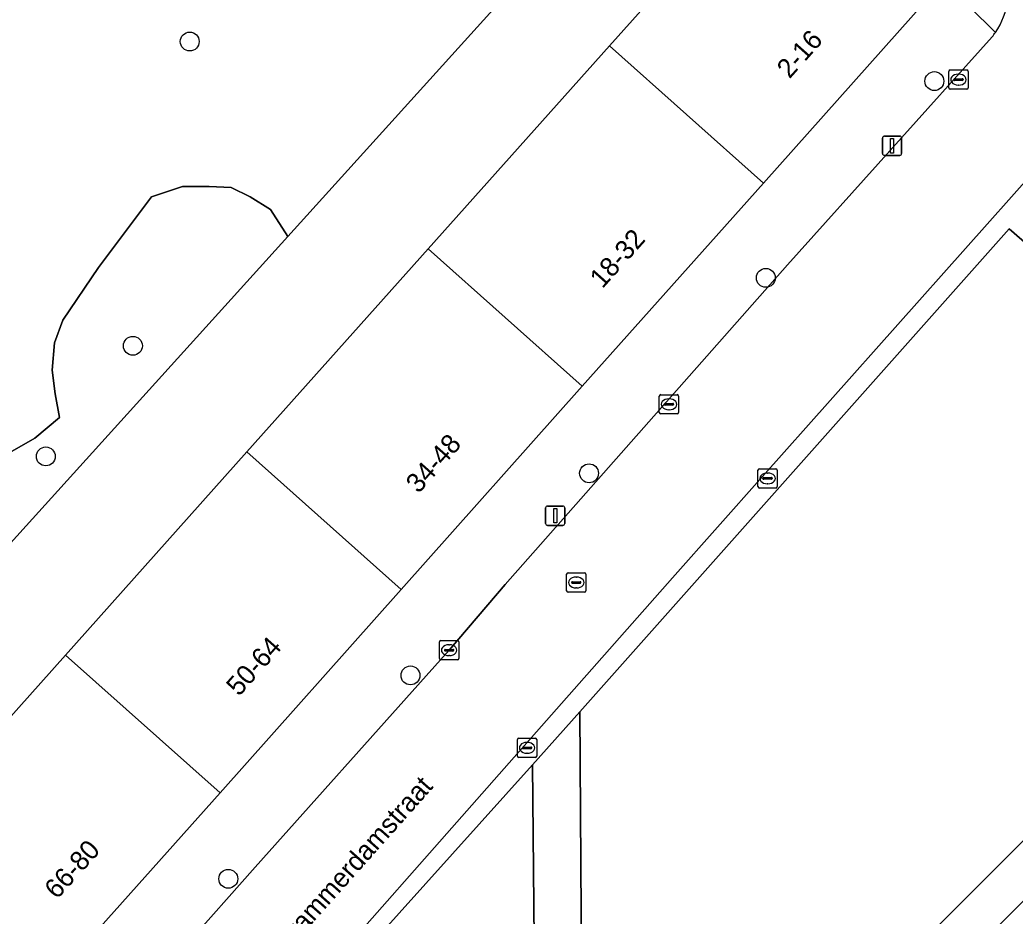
# Model space of a CAD drawing. Extents: x 159888 to 160761, y 384031 to 384750.
# Drawn here: x 160333.6 to 160385.2, y 384297.8 to 384344.2 of the extents above; entities that cross this region are included whole.
import ezdxf

# ---------------------------------------------------------------- set-up
doc = ezdxf.new("R2010")
doc.units = 0
for name, color, linetype in [('IMGEO_Boom', 7, 'Continuous'), ('IMGEO_Erf', 7, 'Continuous'), ('IMGEO_Groenvoorziening', 7, 'Continuous'), ('IMGEO_Kolk', 7, 'Continuous'), ('IMGEO_Lichtmast', 7, 'Continuous'), ('IMGEO_Openbare_ruimte_label', 7, 'Continuous'), ('IMGEO_Pand', 7, 'Continuous'), ('IMGEO_Pand_nummerreeks', 7, 'Continuous'), ('IMGEO_Rijbaan_lokaal_open', 7, 'Continuous'), ('IMGEO_Rioolput', 7, 'Continuous'), ('IMGEO_Voetpad_halfverhard', 7, 'Continuous'), ('IMGEO_Voetpad_open', 7, 'Continuous')]:
    doc.layers.add(name, color=color, linetype=linetype)

msp = doc.modelspace()

# ---------------------------------------------------------------- linework, layer by layer
at = {"layer": 'IMGEO_Boom'}
for centre in [(160342.399, 384343.13), (160380.968, 384341.08), (160372.236, 384330.889), (160339.456, 384327.37), (160334.945, 384321.643), (160363.084, 384320.767), (160353.833, 384310.3), (160344.397, 384299.767)]:
    msp.add_circle(centre, 0.489, dxfattribs=at)
at = {"layer": 'IMGEO_Erf'}
for points in [[(160354.755, 384332.386), (160364.148, 384342.901), (160373.493, 384353.362), (160374.576, 384354.663), (160370.91, 384358.966), (160359.082, 384345.88), (160347.472, 384333.034), (160321.993, 384304.881), (160326.574, 384300.84), (160335.968, 384311.355), (160345.361, 384321.871)], [(160407.134, 384312.362), (160404.095, 384316.885), (160401.57, 384314.532), (160372.039, 384285.135), (160362.772, 384285.007), (160362.837, 384279.095), (160351.699, 384267.85), (160345.439, 384274.748), (160345.355, 384284.72), (160341.199, 384284.583), (160337.275, 384280.219), (160336.483, 384279.562), (160360.504, 384250.764), (160363.191, 384253.558), (160355.746, 384260.844), (160365.773, 384270.9), (160375.799, 384280.956), (160385.826, 384291.012), (160395.852, 384301.068), (160405.753, 384310.998)]]:
    msp.add_lwpolyline(points, close=True, dxfattribs=at)
at = {"layer": 'IMGEO_Groenvoorziening'}
for points in [[(160346.601, 384346.671), (160342.877, 384351.012), (160335.546, 384346.476), (160334.832, 384346.722), (160331.336, 384349.545), (160314.321, 384328.458), (160318.416, 384324.982), (160315.546, 384321.854), (160314.241, 384320.516), (160319.822, 384312.651), (160327.142, 384317.932), (160330.707, 384320.49), (160334.376, 384322.584), (160335.646, 384323.663), (160335.437, 384324.891), (160335.278, 384326.11), (160335.396, 384327.525), (160335.828, 384328.701), (160337.68, 384331.434), (160340.425, 384335.089)], [(160340.425, 384335.089), (160342.026, 384335.628), (160343.406, 384335.615), (160344.546, 384335.562), (160345.527, 384335.084), (160346.587, 384334.422), (160347.472, 384333.034), (160359.082, 384345.88), (160357.029, 384347.606), (160355.178, 384349.66), (160350.544, 384346.722)], [(160321.993, 384304.881), (160347.472, 384333.034), (160346.587, 384334.422), (160345.527, 384335.084), (160344.546, 384335.562), (160343.406, 384335.615), (160342.026, 384335.628), (160340.425, 384335.089), (160337.68, 384331.434), (160335.828, 384328.701), (160335.396, 384327.525), (160335.278, 384326.11), (160335.437, 384324.891), (160335.646, 384323.663), (160334.376, 384322.584), (160330.707, 384320.49)]]:
    msp.add_lwpolyline(points, dxfattribs=at)
for points in [[(160362.609, 384308.421), (160362.749, 384287.577), (160371.557, 384287.736), (160402.753, 384318.884), (160399.209, 384324.159), (160391.497, 384335.159), (160387.746, 384330.904), (160384.849, 384333.43)], [(160343.576, 384287.226), (160360.319, 384287.543), (160360.161, 384305.668)]]:
    msp.add_lwpolyline(points, close=True, dxfattribs=at)
at = {"layer": 'IMGEO_Kolk'}
for p, q in [((160381.716, 384340.73), (160381.716, 384341.582)), ((160381.791, 384341.656), (160382.643, 384341.656)), ((160382.204, 384341.436), (160382.229, 384341.436)), ((160382.717, 384341.582), (160382.717, 384340.73)), ((160381.975, 384341.15), (160381.975, 384341.162)), ((160382.413, 384341.113), (160382.015, 384341.113)), ((160382.018, 384341.199), (160382.416, 384341.199)), ((160382.227, 384340.876), (160382.202, 384340.876)), ((160382.459, 384341.162), (160382.459, 384341.15)), ((160382.643, 384340.656), (160381.791, 384340.656)), ((160366.722, 384323.914), (160366.722, 384324.766)), ((160366.797, 384324.84), (160367.649, 384324.84)), ((160367.723, 384324.766), (160367.723, 384323.914)), ((160366.981, 384324.334), (160366.981, 384324.346)), ((160367.419, 384324.297), (160367.021, 384324.297)), ((160367.024, 384324.383), (160367.422, 384324.383)), ((160367.21, 384324.62), (160367.235, 384324.62)), ((160367.465, 384324.346), (160367.465, 384324.334)), ((160367.649, 384323.84), (160366.797, 384323.84)), ((160367.233, 384324.06), (160367.208, 384324.06)), ((160371.83, 384320.077), (160371.83, 384320.929)), ((160371.905, 384321.003), (160372.757, 384321.003)), ((160372.318, 384320.783), (160372.343, 384320.783)), ((160372.831, 384320.929), (160372.831, 384320.077)), ((160372.089, 384320.497), (160372.089, 384320.509)), ((160372.527, 384320.46), (160372.129, 384320.46)), ((160372.132, 384320.546), (160372.53, 384320.546)), ((160372.341, 384320.223), (160372.316, 384320.223)), ((160372.573, 384320.509), (160372.573, 384320.497)), ((160372.757, 384320.003), (160371.905, 384320.003)), ((160355.335, 384311.18), (160355.335, 384312.032)), ((160355.41, 384312.106), (160356.262, 384312.106)), ((160355.823, 384311.886), (160355.848, 384311.886)), ((160356.336, 384312.032), (160356.336, 384311.18)), ((160355.594, 384311.6), (160355.594, 384311.612)), ((160356.032, 384311.563), (160355.634, 384311.563)), ((160355.637, 384311.649), (160356.035, 384311.649)), ((160356.078, 384311.612), (160356.078, 384311.6)), ((160356.262, 384311.106), (160355.41, 384311.106)), ((160355.846, 384311.326), (160355.821, 384311.326)), ((160359.372, 384306.122), (160359.372, 384306.974)), ((160359.447, 384307.048), (160360.299, 384307.048)), ((160359.86, 384306.828), (160359.885, 384306.828)), ((160360.373, 384306.974), (160360.373, 384306.122)), ((160359.631, 384306.542), (160359.631, 384306.554)), ((160360.069, 384306.505), (160359.671, 384306.505)), ((160359.674, 384306.591), (160360.072, 384306.591)), ((160359.883, 384306.268), (160359.858, 384306.268)), ((160360.115, 384306.554), (160360.115, 384306.542)), ((160360.299, 384306.048), (160359.447, 384306.048))]:
    msp.add_line(p, q, dxfattribs=at)
for points in [[(160381.716, 384340.73), (160381.716, 384341.582)], [(160381.791, 384341.656), (160382.643, 384341.656)], [(160382.717, 384341.582), (160382.717, 384340.73)], [(160382.643, 384340.656), (160381.791, 384340.656)], [(160366.722, 384323.914), (160366.722, 384324.766)], [(160366.797, 384324.84), (160367.649, 384324.84)], [(160367.723, 384324.766), (160367.723, 384323.914)], [(160367.649, 384323.84), (160366.797, 384323.84)], [(160371.83, 384320.077), (160371.83, 384320.929)], [(160371.905, 384321.003), (160372.757, 384321.003)], [(160372.831, 384320.929), (160372.831, 384320.077)], [(160372.757, 384320.003), (160371.905, 384320.003)], [(160355.335, 384311.18), (160355.335, 384312.032)], [(160355.41, 384312.106), (160356.262, 384312.106)], [(160356.336, 384312.032), (160356.336, 384311.18)], [(160356.262, 384311.106), (160355.41, 384311.106)], [(160359.372, 384306.122), (160359.372, 384306.974)], [(160359.447, 384307.048), (160360.299, 384307.048)], [(160360.373, 384306.974), (160360.373, 384306.122)], [(160360.299, 384306.048), (160359.447, 384306.048)]]:
    msp.add_lwpolyline(points, dxfattribs=at)
for centre, radius, start, end in [((160381.793, 384341.58), 0.0765, 91.552, 178.448), ((160381.793, 384341.58), 0.0765, 91.552, 178.448), ((160382.641, 384341.58), 0.0765, 1.552, 88.448), ((160382.641, 384341.58), 0.0765, 1.552, 88.448), ((160382.015, 384341.159), 0.0403, 85.8775, 175.7526), ((160382.012, 384341.149), 0.0366, 178.938, 274.7102), ((160382.416, 384341.156), 0.043, 264.8664, 352.4533), ((160382.42, 384341.161), 0.0386, 1.7309, 96.639), ((160381.793, 384340.732), 0.0765, 181.552, 268.448), ((160381.793, 384340.732), 0.0765, 181.552, 268.448), ((160382.641, 384340.732), 0.0765, 271.552, 358.448), ((160382.641, 384340.732), 0.0765, 271.552, 358.448), ((160366.799, 384324.764), 0.0765, 91.552, 178.448), ((160366.799, 384324.764), 0.0765, 91.552, 178.448), ((160367.647, 384324.764), 0.0765, 1.552, 88.448), ((160367.647, 384324.764), 0.0765, 1.552, 88.448), ((160367.021, 384324.343), 0.0403, 85.8775, 175.7526), ((160367.018, 384324.333), 0.0366, 178.938, 274.7102), ((160367.422, 384324.34), 0.043, 264.8664, 352.4533), ((160367.426, 384324.345), 0.0386, 1.7309, 96.639), ((160366.799, 384323.916), 0.0765, 181.552, 268.448), ((160366.799, 384323.916), 0.0765, 181.552, 268.448), ((160367.647, 384323.916), 0.0765, 271.552, 358.448), ((160367.647, 384323.916), 0.0765, 271.552, 358.448), ((160371.907, 384320.927), 0.0765, 91.552, 178.448), ((160371.907, 384320.927), 0.0765, 91.552, 178.448), ((160372.755, 384320.927), 0.0765, 1.552, 88.448), ((160372.755, 384320.927), 0.0765, 1.552, 88.448), ((160372.129, 384320.506), 0.0403, 85.8775, 175.7526), ((160372.126, 384320.496), 0.0366, 178.938, 274.7102), ((160372.53, 384320.503), 0.043, 264.8664, 352.4533), ((160372.534, 384320.508), 0.0386, 1.7309, 96.639), ((160371.907, 384320.079), 0.0765, 181.552, 268.448), ((160371.907, 384320.079), 0.0765, 181.552, 268.448), ((160372.755, 384320.079), 0.0765, 271.552, 358.448), ((160372.755, 384320.079), 0.0765, 271.552, 358.448), ((160355.412, 384312.03), 0.0765, 91.552, 178.448), ((160355.412, 384312.03), 0.0765, 91.552, 178.448), ((160356.26, 384312.03), 0.0765, 1.552, 88.448), ((160356.26, 384312.03), 0.0765, 1.552, 88.448), ((160355.634, 384311.609), 0.0403, 85.8775, 175.7526), ((160355.631, 384311.599), 0.0366, 178.938, 274.7102), ((160356.035, 384311.606), 0.043, 264.8664, 352.4533), ((160356.039, 384311.611), 0.0386, 1.7309, 96.639), ((160355.412, 384311.182), 0.0765, 181.552, 268.448), ((160355.412, 384311.182), 0.0765, 181.552, 268.448), ((160356.26, 384311.182), 0.0765, 271.552, 358.448), ((160356.26, 384311.182), 0.0765, 271.552, 358.448), ((160359.449, 384306.972), 0.0765, 91.552, 178.448), ((160359.449, 384306.972), 0.0765, 91.552, 178.448), ((160360.297, 384306.972), 0.0765, 1.552, 88.448), ((160360.297, 384306.972), 0.0765, 1.552, 88.448), ((160359.671, 384306.551), 0.0403, 85.8775, 175.7526), ((160359.668, 384306.541), 0.0366, 178.938, 274.7102), ((160360.072, 384306.548), 0.043, 264.8664, 352.4533), ((160360.076, 384306.553), 0.0386, 1.7309, 96.639), ((160359.449, 384306.124), 0.0765, 181.552, 268.448), ((160359.449, 384306.124), 0.0765, 181.552, 268.448), ((160360.297, 384306.124), 0.0765, 271.552, 358.448), ((160360.297, 384306.124), 0.0765, 271.552, 358.448)]:
    msp.add_arc(centre, radius, start, end, dxfattribs=at)
for centre, major_axis, ratio, start_param, end_param in [((160382.203, 384341.156), (-0.387, 0.002), 0.722429, 4.712389, 7.853982), ((160382.228, 384341.156), (-0.39, 0.002), 0.717154, 1.570796, 4.712389), ((160367.209, 384324.34), (-0.387, 0.002), 0.722429, 4.712389, 7.853982), ((160367.234, 384324.34), (-0.39, 0.002), 0.717154, 1.570796, 4.712389), ((160372.317, 384320.503), (-0.387, 0.002), 0.722429, 4.712389, 7.853982), ((160372.342, 384320.503), (-0.39, 0.002), 0.717154, 1.570796, 4.712389), ((160355.822, 384311.606), (-0.387, 0.002), 0.722429, 4.712389, 7.853982), ((160355.847, 384311.606), (-0.39, 0.002), 0.717154, 1.570796, 4.712389), ((160359.859, 384306.548), (-0.387, 0.002), 0.722429, 4.712389, 7.853982), ((160359.884, 384306.548), (-0.39, 0.002), 0.717154, 1.570796, 4.712389)]:
    msp.add_ellipse(centre, major_axis=major_axis, ratio=ratio, start_param=start_param, end_param=end_param, dxfattribs=at)
at = {"layer": 'IMGEO_Lichtmast'}
for p, q in [((160378.382, 384338.23), (160379.172, 384338.23)), ((160379.172, 384338.23), (160378.382, 384338.23)), ((160378.282, 384337.33), (160378.282, 384338.13)), ((160378.282, 384338.13), (160378.282, 384337.33)), ((160379.272, 384338.13), (160379.272, 384337.33)), ((160379.272, 384337.33), (160379.272, 384338.13)), ((160379.172, 384337.23), (160378.382, 384337.23)), ((160378.382, 384337.23), (160379.172, 384337.23)), ((160360.835, 384318.171), (160360.835, 384318.971)), ((160360.835, 384318.971), (160360.835, 384318.171)), ((160360.935, 384319.071), (160361.725, 384319.071)), ((160361.725, 384319.071), (160360.935, 384319.071)), ((160361.825, 384318.971), (160361.825, 384318.171)), ((160361.825, 384318.171), (160361.825, 384318.971)), ((160361.725, 384318.071), (160360.935, 384318.071)), ((160360.935, 384318.071), (160361.725, 384318.071))]:
    msp.add_line(p, q, dxfattribs=at)
for points in [[(160378.702, 384338.105), (160378.852, 384338.105), (160378.852, 384337.355), (160378.702, 384337.355), (160378.702, 384338.105)], [(160361.255, 384318.946), (160361.405, 384318.946), (160361.405, 384318.196), (160361.255, 384318.196), (160361.255, 384318.946)]]:
    msp.add_lwpolyline(points, dxfattribs=at)
for centre, start, end in [((160378.382, 384338.13), 90, 180), ((160378.382, 384338.13), 90, 180), ((160379.172, 384338.13), 0, 90), ((160379.172, 384338.13), 360, 90), ((160378.382, 384337.33), 180, 270), ((160378.382, 384337.33), 180, 270), ((160379.172, 384337.33), 270, 0), ((160379.172, 384337.33), 270, 0), ((160360.935, 384318.971), 90, 180), ((160360.935, 384318.971), 90, 180), ((160361.725, 384318.971), 0, 90), ((160361.725, 384318.971), 360, 90), ((160360.935, 384318.171), 180, 270), ((160360.935, 384318.171), 180, 270), ((160361.725, 384318.171), 270, 0), ((160361.725, 384318.171), 270, 0)]:
    msp.add_arc(centre, 0.1, start, end, dxfattribs=at)
at = {"layer": 'IMGEO_Pand'}
for points in [[(160364.148, 384342.901), (160372.116, 384335.798), (160381.45, 384346.268), (160373.493, 384353.362)], [(160354.755, 384332.386), (160362.733, 384325.273), (160372.116, 384335.798), (160364.148, 384342.901)], [(160354.755, 384332.386), (160345.361, 384321.871), (160353.35, 384314.748), (160362.733, 384325.273)], [(160343.967, 384304.224), (160353.35, 384314.748), (160345.361, 384321.871), (160335.968, 384311.355)], [(160343.967, 384304.224), (160335.968, 384311.355), (160326.574, 384300.84), (160330.004, 384297.782), (160334.584, 384293.699)]]:
    msp.add_lwpolyline(points, close=True, dxfattribs=at)
at = {"layer": 'IMGEO_Rijbaan_lokaal_open'}
for points in [[(160383.963, 384343.377), (160373.369, 384331.56), (160358.734, 384315.005), (160355.836, 384311.606), (160354.645, 384310.274), (160345.783, 384300.371), (160342.137, 384296.259), (160335.028, 384288.426), (160333.603, 384286.83), (160331.755, 384284.956), (160329.563, 384283.059), (160327.209, 384281.326), (160320.493, 384276.397), (160319.163, 384275.415), (160318.454, 384274.829), (160317.834, 384274.312)], [(160367.398, 384315.345), (160372.06, 384320.608), (160386.091, 384336.349), (160387.995, 384338.559)], [(160316.352, 384271.463), (160319.071, 384267.868), (160319.303, 384267.551), (160320.163, 384268.187), (160325.613, 384272.322), (160329.833, 384275.348), (160333.576, 384278.079), (160335.984, 384279.983), (160336.104, 384280.105), (160336.716, 384280.731), (160338.331, 384282.617), (160345.01, 384289.972), (160361.399, 384308.557), (160367.398, 384315.345)]]:
    msp.add_lwpolyline(points, dxfattribs=at)
for centre, radius, start, end in [((160381.036, 384345.741), 3.762, 325.3172, 353.4534), ((160381.37, 384345.493), 3.347, 320.7858, 325.5567)]:
    msp.add_arc(centre, radius, start, end, dxfattribs=at)
at = {"layer": 'IMGEO_Rioolput'}
for p, q in [((160361.92, 384314.685), (160361.92, 384315.537)), ((160361.995, 384315.611), (160362.847, 384315.611)), ((160362.921, 384315.537), (160362.921, 384314.685)), ((160362.179, 384315.105), (160362.179, 384315.117)), ((160362.617, 384315.068), (160362.219, 384315.068)), ((160362.222, 384315.154), (160362.62, 384315.154)), ((160362.408, 384315.391), (160362.433, 384315.391)), ((160362.663, 384315.117), (160362.663, 384315.105)), ((160362.847, 384314.611), (160361.995, 384314.611)), ((160362.431, 384314.831), (160362.406, 384314.831))]:
    msp.add_line(p, q, dxfattribs=at)
for points in [[(160361.92, 384314.685), (160361.92, 384315.537)], [(160361.995, 384315.611), (160362.847, 384315.611)], [(160362.921, 384315.537), (160362.921, 384314.685)], [(160362.847, 384314.611), (160361.995, 384314.611)]]:
    msp.add_lwpolyline(points, dxfattribs=at)
for centre, radius, start, end in [((160361.997, 384315.535), 0.0765, 91.552, 178.448), ((160361.997, 384315.535), 0.0765, 91.552, 178.448), ((160362.845, 384315.535), 0.0765, 1.552, 88.448), ((160362.845, 384315.535), 0.0765, 1.552, 88.448), ((160362.219, 384315.114), 0.0403, 85.8775, 175.7526), ((160362.216, 384315.104), 0.0366, 178.938, 274.7102), ((160362.62, 384315.111), 0.043, 264.8664, 352.4533), ((160362.624, 384315.116), 0.0386, 1.7309, 96.639), ((160361.997, 384314.687), 0.0765, 181.552, 268.448), ((160361.997, 384314.687), 0.0765, 181.552, 268.448), ((160362.845, 384314.687), 0.0765, 271.552, 358.448), ((160362.845, 384314.687), 0.0765, 271.552, 358.448)]:
    msp.add_arc(centre, radius, start, end, dxfattribs=at)
for centre, major_axis, ratio, start_param, end_param in [((160362.407, 384315.111), (-0.387, 0.002), 0.722429, 4.712389, 7.853982), ((160362.432, 384315.111), (-0.39, 0.002), 0.717154, 1.570796, 4.712389)]:
    msp.add_ellipse(centre, major_axis=major_axis, ratio=ratio, start_param=start_param, end_param=end_param, dxfattribs=at)
at = {"layer": 'IMGEO_Voetpad_halfverhard'}
msp.add_lwpolyline([(160401.57, 384314.532), (160404.095, 384316.885), (160402.753, 384318.884), (160371.557, 384287.736), (160362.749, 384287.577), (160362.609, 384308.421), (160360.161, 384305.668), (160360.319, 384287.543), (160343.576, 384287.226), (160341.199, 384284.583), (160345.355, 384284.72), (160362.772, 384285.007), (160372.039, 384285.135)], close=True, dxfattribs=at)
at = {"layer": 'IMGEO_Voetpad_open'}
for points in [[(160353.925, 384379.322), (160350.858, 384375.538), (160351.227, 384374.884), (160353.151, 384372.682), (160356.226, 384375.192), (160358.705, 384372.155), (160359.244, 384372.659), (160367.457, 384363.019), (160369.023, 384361.181), (160370.91, 384358.966), (160374.576, 384354.663), (160373.493, 384353.362), (160381.45, 384346.268), (160384.13, 384343.6)], [(160384.13, 384343.6), (160381.45, 384346.268), (160372.116, 384335.798), (160362.733, 384325.273), (160353.35, 384314.748), (160343.967, 384304.224), (160334.584, 384293.699), (160331.935, 384291.025), (160329.749, 384288.44), (160312.595, 384275.443), (160316.352, 384271.463)], [(160354.645, 384310.274), (160355.836, 384311.606), (160358.734, 384315.005), (160373.369, 384331.56), (160383.963, 384343.377)], [(160333.927, 384277.642), (160336.483, 384279.562), (160337.275, 384280.219), (160341.199, 384284.583), (160343.576, 384287.226), (160360.161, 384305.668), (160362.609, 384308.421), (160384.849, 384333.43), (160387.746, 384330.904), (160391.497, 384335.159), (160388.52, 384338.959)], [(160387.995, 384338.559), (160386.091, 384336.349), (160372.06, 384320.608), (160367.398, 384315.345), (160361.399, 384308.557), (160345.01, 384289.972), (160338.331, 384282.617), (160336.716, 384280.731), (160336.104, 384280.105), (160335.984, 384279.983), (160333.576, 384278.079), (160329.833, 384275.348), (160325.613, 384272.322), (160320.163, 384268.187), (160319.303, 384267.551), (160318.92, 384266.275), (160333.927, 384277.642)], [(160317.834, 384274.312), (160318.454, 384274.829), (160319.163, 384275.415), (160320.493, 384276.397), (160327.209, 384281.326), (160329.563, 384283.059), (160331.755, 384284.956), (160331.394, 384285.301), (160334.662, 384288.766), (160335.028, 384288.426), (160342.137, 384296.259), (160345.783, 384300.371), (160354.645, 384310.274)]]:
    msp.add_lwpolyline(points, dxfattribs=at)
for centre, radius, start, end in [((160381.036, 384345.741), 3.762, 325.3172, 353.4534), ((160381.37, 384345.493), 3.347, 320.7858, 325.5567)]:
    msp.add_arc(centre, radius, start, end, dxfattribs=at)

# ---------------------------------------------------------------- texts
at = {"layer": 'IMGEO_Openbare_ruimte_label'}
msp.add_text('Swammerdamstraat', height=1, rotation=48.3236, dxfattribs=at).set_placement((160347.088, 384295.578))
at = {"layer": 'IMGEO_Pand_nummerreeks'}
for s, rotation, p in [('2-16', 48.3665, (160373.467, 384341.166)), ('18-32', 48.221, (160363.775, 384330.301)), ('34-48', 48.4385, (160354.252, 384319.682)), ('50-64', 48.4533, (160344.952, 384309.177)), ('66-80', 47.9508, (160335.524, 384298.668))]:
    msp.add_text(s, height=1, rotation=rotation, dxfattribs=at).set_placement(p)

doc.saveas('drawing.dxf')
